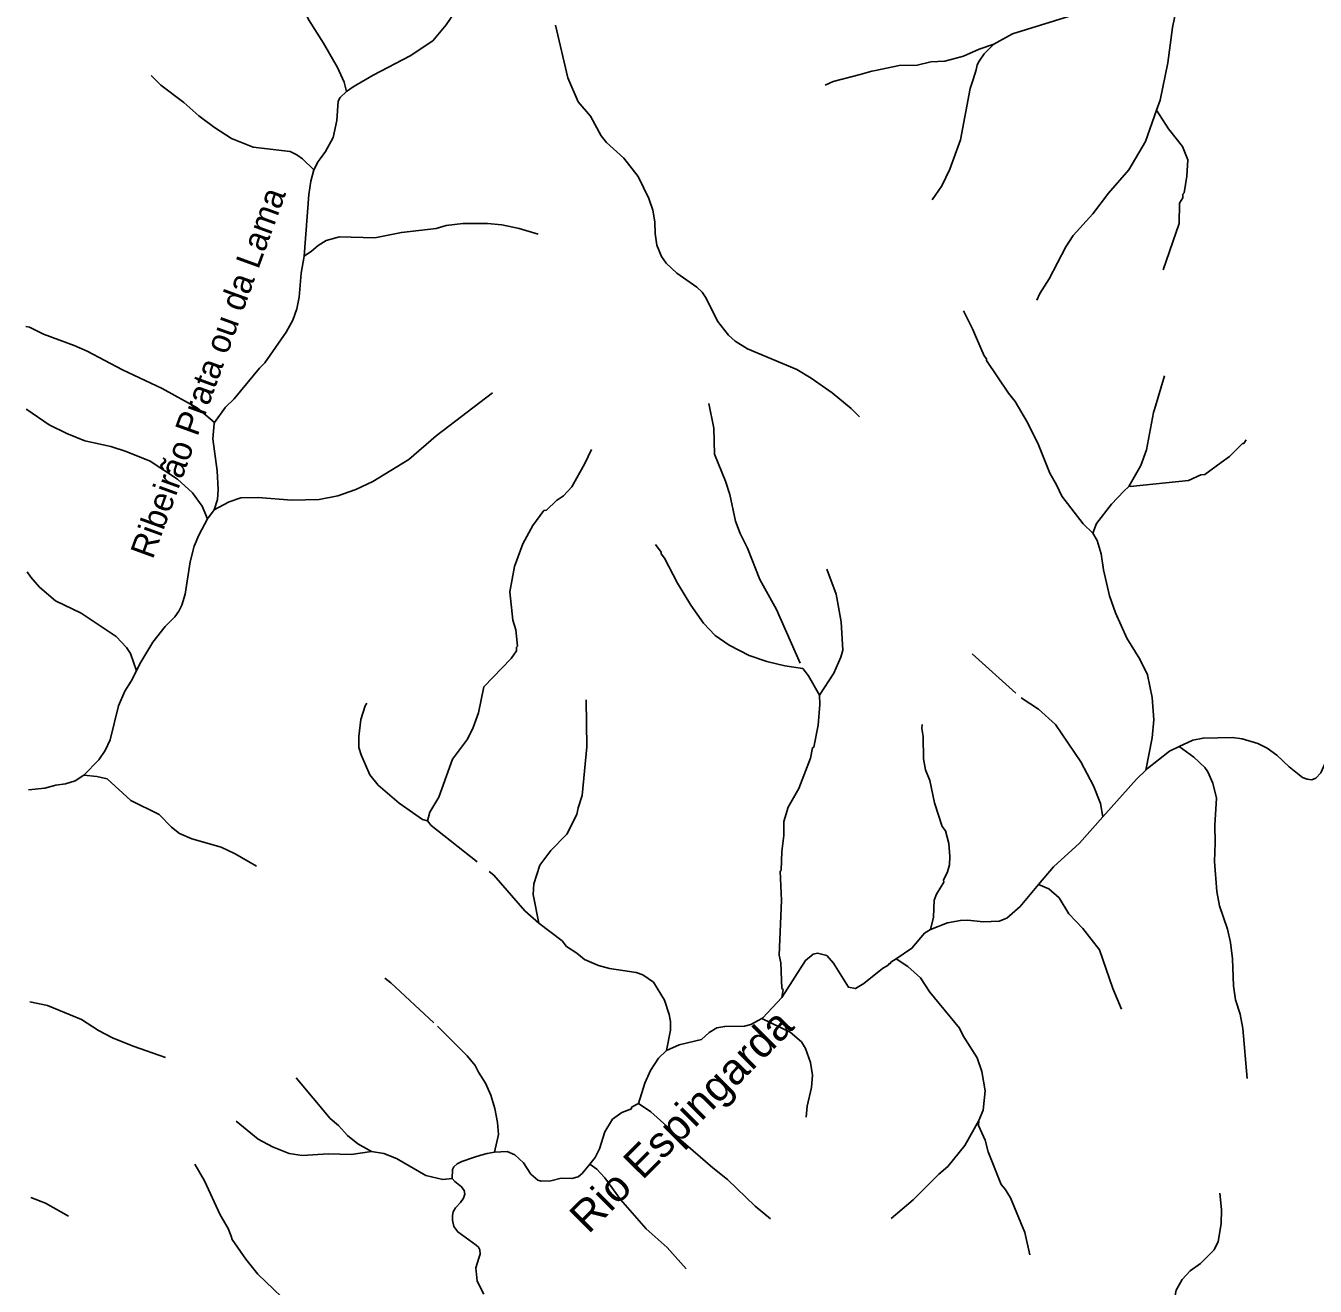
# Model space of a CAD drawing. Extents: x 280.4 to 335.6, y 8893.9 to 8949.5.
# Drawn here: x 280.52 to 288.97, y 8929.23 to 8937.49 of the extents above; entities that cross this region are included whole.
import ezdxf
from ezdxf.enums import TextEntityAlignment as Align

# ---------------------------------------------------------------- set-up
doc = ezdxf.new("R2010")
doc.units = 0
doc.header["$LTSCALE"] = 0.064
doc.linetypes.add('LONG_DASHED', pattern=[7.5, 6, -1.5])
doc.layers.add('61', color=7, linetype='Continuous')
doc.layers.add('7', color=7, linetype='Continuous', lineweight=25)
doc.layers.add('9', color=7, linetype='LONG_DASHED', lineweight=25)

msp = doc.modelspace()

# ---------------------------------------------------------------- linework, layer by layer
at = {"layer": '7'}
msp.add_line((281.7518, 8934.3135), (281.7096, 8934.2547), dxfattribs=at)
for points in [[(281.967, 8938.9139), (281.9473, 8938.7988), (281.9521, 8938.6717), (282.0016, 8938.4595), (282.0238, 8938.3645), (282.1057, 8938.1592), (282.2165, 8937.9498), (282.2476, 8937.8705), (282.2972, 8937.696), (282.3705, 8937.5274), (282.4689, 8937.3717), (282.5597, 8937.2125), (282.6042, 8937.1171), (282.6197, 8937.0564)], [(282.6197, 8937.0564), (282.6415, 8937.0718), (282.6624, 8937.0855), (282.7939, 8937.1632), (283.0361, 8937.2893), (283.1847, 8937.388), (283.2726, 8937.4919), (283.4685, 8937.7801)], [(285.9795, 8934.9237), (285.9257, 8934.9786), (285.8014, 8935.0821), (285.663, 8935.1783), (285.5691, 8935.2351), (285.2459, 8935.3688), (285.1656, 8935.4208), (285.122, 8935.4595), (285.0489, 8935.5507), (284.9765, 8935.702), (284.9485, 8935.7415), (284.9153, 8935.773), (284.7827, 8935.8659), (284.7124, 8935.9298), (284.6835, 8935.9743), (284.6516, 8936.0481), (284.6403, 8936.1257), (284.6387, 8936.2016), (284.6258, 8936.2792), (284.6007, 8936.3545), (284.5304, 8936.4985), (284.4369, 8936.619), (284.3233, 8936.722), (284.2866, 8936.7663), (284.2185, 8936.895), (284.1372, 8936.9881), (284.0697, 8937.1445), (283.9876, 8937.4914)], [(281.3389, 8937.1603), (281.4028, 8937.0978), (281.5546, 8936.9844), (281.6524, 8936.8962), (281.7549, 8936.8189), (281.8667, 8936.7474), (282.0086, 8936.6914), (282.2502, 8936.6619), (282.2942, 8936.6414), (282.331, 8936.6142), (282.4048, 8936.5418)], [(282.4048, 8936.5418), (282.4346, 8936.597), (282.4537, 8936.6241), (282.4813, 8936.6623), (282.5315, 8936.7535), (282.5564, 8936.8662), (282.5651, 8936.9922), (282.5772, 8937.0165), (282.6197, 8937.0564)], [(282.3422, 8935.9758), (282.3726, 8936.38), (282.3855, 8936.4672), (282.4048, 8936.5418)], [(283.8759, 8936.12), (283.7496, 8936.1584), (283.6363, 8936.181), (283.5424, 8936.1903), (283.3824, 8936.1904), (283.2726, 8936.1784), (283.2063, 8936.1581), (282.9787, 8936.1329), (282.806, 8936.0978), (282.5742, 8936.1038), (282.4867, 8936.0787), (282.4329, 8936.0477), (282.3911, 8936.0093), (282.3422, 8935.9758)], [(281.7555, 8934.8857), (281.8277, 8934.9864), (281.8842, 8935.0417), (282.0485, 8935.2427), (282.0836, 8935.278), (282.2243, 8935.4795), (282.2673, 8935.5563), (282.2942, 8935.6323), (282.3085, 8935.7084), (282.3233, 8935.8643), (282.3422, 8935.9758)], [(280.5185, 8935.5165), (280.5422, 8935.5104), (280.6336, 8935.4647), (280.8357, 8935.3908), (280.9195, 8935.3536), (281.1518, 8935.2329), (281.4121, 8935.109), (281.6417, 8934.983), (281.7555, 8934.8857)], [(283.5753, 8935.0811), (283.2068, 8934.8001), (283.027, 8934.6446), (282.7926, 8934.4997), (282.6808, 8934.4484), (282.5622, 8934.4056), (282.4398, 8934.3828), (282.2615, 8934.377), (282.0416, 8934.3961), (281.9272, 8934.393), (281.8504, 8934.3676), (281.8129, 8934.3474), (281.7518, 8934.3135)], [(280.5217, 8934.9745), (280.5243, 8934.9727), (280.6721, 8934.8714), (280.7864, 8934.8142), (280.9052, 8934.7665), (281.075, 8934.7305), (281.1769, 8934.6965), (281.3325, 8934.6329), (281.5122, 8934.5144), (281.6104, 8934.4258), (281.6732, 8934.3376), (281.7096, 8934.2547)], [(281.7518, 8934.3135), (281.7747, 8934.3822), (281.7785, 8934.4484), (281.7729, 8934.5704), (281.7427, 8934.7798), (281.7523, 8934.8812), (281.7555, 8934.8857)], [(281.2433, 8933.2589), (281.2666, 8933.3045), (281.3504, 8933.4471), (281.4307, 8933.5501), (281.4942, 8933.6139), (281.5213, 8933.6502), (281.5407, 8933.6901), (281.5618, 8933.7612), (281.5956, 8933.9731), (281.6223, 8934.0771), (281.6517, 8934.1489), (281.7096, 8934.2547)], [(280.5279, 8933.9075), (280.5517, 8933.8727), (280.6091, 8933.8086), (280.713, 8933.719), (280.8821, 8933.638), (281.1102, 8933.4851), (281.179, 8933.4131), (281.2054, 8933.3719), (281.2433, 8933.2589)], [(280.8997, 8932.5762), (280.9962, 8932.6757), (281.0388, 8932.7377), (281.0702, 8932.8065), (281.1265, 8933.0303), (281.1666, 8933.1271), (281.209, 8933.1919), (281.2433, 8933.2589)], [(289.193, 8932.8412), (289.1727, 8932.841), (289.1187, 8932.8127), (289.1163, 8932.8003), (289.1016, 8932.7925), (289.07, 8932.7449), (289.0018, 8932.5912), (288.9694, 8932.5555), (288.9433, 8932.5459), (288.9115, 8932.5491), (288.8818, 8932.5612), (288.7945, 8932.631), (288.7147, 8932.7061), (288.6507, 8932.7524), (288.5889, 8932.784), (288.4859, 8932.813), (288.4226, 8932.8224), (288.23, 8932.8191), (288.1639, 8932.8053), (288.0744, 8932.7635)], [(288.0744, 8932.7635), (288.0112, 8932.7339), (287.8666, 8932.6199), (287.8557, 8932.6094)], [(280.5362, 8932.4799), (280.6433, 8932.4909), (280.7143, 8932.5105), (280.7788, 8932.5188), (280.8414, 8932.5392), (280.8997, 8932.5762)], [(282.0295, 8931.9786), (281.8896, 8932.061), (281.7991, 8932.104), (281.6072, 8932.1586), (281.5251, 8932.1925), (281.473, 8932.2354), (281.3922, 8932.3186), (281.2069, 8932.4094), (281.0522, 8932.5507), (280.9836, 8932.5664), (280.8997, 8932.5762)], [(287.8557, 8932.6094), (287.794, 8932.5501), (287.5737, 8932.3016)], [(287.5737, 8932.3016), (287.421, 8932.1294), (287.2498, 8931.9743), (287.153, 8931.8589)], [(287.153, 8931.8589), (287.0328, 8931.7157), (286.9455, 8931.6393), (286.8937, 8931.6198), (286.7899, 8931.6135), (286.689, 8931.6261), (286.6404, 8931.6233), (286.5571, 8931.6073), (286.4442, 8931.5636)], [(286.4442, 8931.5636), (286.4064, 8931.5412), (286.3232, 8931.4414), (286.219, 8931.3726)], [(286.219, 8931.3726), (286.1854, 8931.3504), (286.1832, 8931.342), (286.1743, 8931.3411), (286.1681, 8931.3313), (286.1312, 8931.3085), (286.0087, 8931.2099), (285.9533, 8931.177), (285.9085, 8931.1854), (285.809, 8931.3437), (285.7651, 8931.3936), (285.7055, 8931.4085), (285.6764, 8931.4027), (285.6253, 8931.3618), (285.4711, 8931.1195), (285.47, 8931.1183)], [(281.434, 8930.725), (281.2209, 8930.7989), (281.0861, 8930.8542), (280.995, 8930.9022), (280.8837, 8930.9736), (280.6614, 8931.0669), (280.5444, 8931.0912)], [(285.47, 8931.1183), (285.3457, 8930.9854), (285.3397, 8930.982)], [(285.3397, 8930.982), (285.268, 8930.9415), (285.2256, 8930.9309), (285.0968, 8930.929), (285.0444, 8930.919), (284.9956, 8930.8904), (284.9445, 8930.8429), (284.7995, 8930.8086), (284.7162, 8930.7708)], [(284.7162, 8930.7708), (284.6632, 8930.7211), (284.6097, 8930.6403), (284.5735, 8930.5569), (284.5328, 8930.4241), (284.5312, 8930.4232)], [(284.5312, 8930.4232), (284.487, 8930.3994), (284.4859, 8930.3883), (284.4239, 8930.3655), (284.3614, 8930.3206), (284.3126, 8930.238), (284.2757, 8930.1277), (284.2488, 8930.0708), (284.2135, 8930.0274)], [(283.4505, 8930.0706), (283.3752, 8930.043), (283.3434, 8930.0277), (283.3222, 8930.01), (283.3145, 8929.9913), (283.3124, 8929.9327)], [(283.5892, 8930.1052), (283.5405, 8930.0958), (283.4987, 8930.0863), (283.4505, 8930.0706)], [(284.2135, 8930.0274), (284.1635, 8929.966), (284.1373, 8929.9435), (284.0957, 8929.9327), (284.0264, 8929.9354), (283.9583, 8929.9179), (283.8942, 8929.915), (283.8735, 8929.9206), (283.8279, 8929.9611), (283.7787, 8930.036), (283.7224, 8930.0876), (283.6714, 8930.1099), (283.5892, 8930.1052)], [(283.3124, 8929.9327), (283.3294, 8929.9132), (283.373, 8929.8785), (283.3909, 8929.8546), (283.3943, 8929.8303), (283.3866, 8929.8039), (283.3663, 8929.7744), (283.3332, 8929.74), (283.3178, 8929.7143), (283.3128, 8929.6891), (283.3131, 8929.6592), (283.3215, 8929.6178), (283.3481, 8929.5826), (283.4681, 8929.4956), (283.4834, 8929.4816), (283.4931, 8929.4643), (283.4949, 8929.4358), (283.4873, 8929.4113), (283.4667, 8929.3472), (283.4743, 8929.2592), (283.519, 8929.1736)], [(280.5519, 8929.8073), (280.6477, 8929.7706), (280.799, 8929.6847)]]:
    msp.add_lwpolyline(points, dxfattribs=at)
at = {"layer": '9'}
for points in [[(286.86, 8937.3667), (286.9819, 8937.4331), (287.3632, 8937.5528), (287.5977, 8937.6453), (287.7712, 8937.7255), (288.0004, 8937.8186), (288.0644, 8937.861)], [(287.9256, 8936.9331), (287.9492, 8936.9999), (288.0006, 8937.2435), (288.031, 8937.4755), (288.0551, 8937.5918), (288.0676, 8937.7185), (288.0644, 8937.861)], [(285.7555, 8937.0966), (285.808, 8937.1208), (285.9839, 8937.1681), (286.0596, 8937.1887), (286.0851, 8937.1941), (286.2388, 8937.2267), (286.3581, 8937.2286), (286.4469, 8937.2506), (286.5396, 8937.2555), (286.662, 8937.2871), (286.7627, 8937.3323), (286.86, 8937.3667)], [(286.4557, 8936.3456), (286.5201, 8936.4378), (286.5711, 8936.5464), (286.6412, 8936.7381), (286.7048, 8937.0756), (286.7242, 8937.1341), (286.7435, 8937.1973), (286.7514, 8937.2306), (286.763, 8937.2538), (286.7968, 8937.3026), (286.86, 8937.3667)], [(287.1408, 8935.689), (287.1613, 8935.7315), (287.2232, 8935.8275), (287.3308, 8936.0377), (287.3804, 8936.1129), (287.5084, 8936.2533), (287.6118, 8936.3887), (287.7437, 8936.5422), (287.8533, 8936.7279), (287.9256, 8936.9331)], [(287.9689, 8935.8863), (288.0728, 8936.1917), (288.0766, 8936.3232), (288.0989, 8936.3593), (288.0983, 8936.3837), (288.1061, 8936.3919), (288.1237, 8936.5007), (288.1315, 8936.6079), (288.0965, 8936.6952), (288.0032, 8936.8115), (287.9256, 8936.9331)], [(286.6608, 8935.6181), (286.7204, 8935.5007), (286.7466, 8935.4398), (286.7964, 8935.3243), (286.8122, 8935.3044), (286.8112, 8935.293), (286.955, 8935.0799), (286.9988, 8935.0245), (287.0812, 8934.8878), (287.1528, 8934.7399), (287.2277, 8934.5551), (287.2711, 8934.4791), (287.3045, 8934.4032), (287.4447, 8934.2227), (287.5093, 8934.1605)], [(287.9776, 8935.1933), (287.912, 8934.9713), (287.9064, 8934.9523), (287.859, 8934.7073), (287.8226, 8934.605), (287.7434, 8934.4663)], [(284.9924, 8935.0108), (285.0253, 8934.8495), (285.0307, 8934.6796), (285.1025, 8934.5016), (285.1295, 8934.4145), (285.1666, 8934.2409), (285.1982, 8934.1602), (285.2468, 8934.0627), (285.3265, 8933.8572), (285.4368, 8933.6604), (285.6076, 8933.2739)], [(288.5134, 8934.7726), (288.4979, 8934.7483), (288.489, 8934.7483), (288.4029, 8934.6643), (288.3482, 8934.6244), (288.2418, 8934.5467), (288.2155, 8934.5428), (288.1344, 8934.5063), (287.7434, 8934.4663)], [(284.224, 8934.7102), (284.181, 8934.6179), (284.0948, 8934.4646), (284.04, 8934.4067), (283.9955, 8934.3749), (283.9294, 8934.3121), (283.9131, 8934.3095), (283.8395, 8934.2127), (283.7738, 8934.0913), (283.7203, 8933.9441), (283.689, 8933.778), (283.7096, 8933.5924), (283.7288, 8933.5277), (283.74, 8933.4218), (283.7338, 8933.4134), (283.7335, 8933.3908), (283.6973, 8933.3411), (283.5183, 8933.1539), (283.4839, 8932.9832), (283.4492, 8932.8887), (283.4116, 8932.8121), (283.3147, 8932.6816), (283.2237, 8932.4313), (283.1645, 8932.3323), (283.1502, 8932.2762)], [(287.7434, 8934.4663), (287.7116, 8934.4369), (287.6297, 8934.3516), (287.5322, 8934.2256), (287.5093, 8934.1605)], [(284.6439, 8934.0867), (284.6799, 8934.0375), (284.681, 8934.0263), (284.7025, 8933.9977), (284.7867, 8933.8343), (284.875, 8933.6907), (284.9582, 8933.5715), (285.0349, 8933.4899), (285.1252, 8933.4278), (285.2577, 8933.3607), (285.3722, 8933.3216), (285.4913, 8933.293), (285.6076, 8933.2739)], [(287.5093, 8934.1605), (287.5363, 8934.1143), (287.5624, 8934.0259), (287.5786, 8933.9204), (287.617, 8933.7508), (287.6569, 8933.6404), (287.7319, 8933.4729), (287.8169, 8933.3351), (287.8671, 8933.2333), (287.8964, 8933.0839), (287.9076, 8932.9392), (287.898, 8932.8208), (287.8557, 8932.6094)], [(285.7175, 8933.099), (285.811, 8933.2447), (285.8571, 8933.3479), (285.87, 8933.395), (285.8607, 8933.5812), (285.8271, 8933.7622), (285.7663, 8933.926)], [(286.7187, 8933.3704), (287.0383, 8933.0827), (287.1528, 8933.0079), (287.2637, 8932.908), (287.4304, 8932.6636), (287.5134, 8932.5057), (287.5587, 8932.3898), (287.5737, 8932.3016)], [(285.6076, 8933.2739), (285.6461, 8933.227), (285.7175, 8933.099)], [(285.7175, 8933.099), (285.721, 8933.0395), (285.7083, 8932.9039), (285.6815, 8932.7601), (285.672, 8932.7558), (285.6591, 8932.6866), (285.5814, 8932.4879), (285.5121, 8932.3666), (285.4852, 8932.2722), (285.4851, 8932.1807), (285.4705, 8932.0755), (285.4672, 8931.9502), (285.4611, 8931.946), (285.4688, 8931.7552), (285.4546, 8931.3967), (285.464, 8931.3456), (285.472, 8931.1766), (285.4797, 8931.1703), (285.47, 8931.1183)], [(282.7536, 8933.0475), (282.7419, 8933.0298), (282.7135, 8932.9398), (282.7006, 8932.8287), (282.7005, 8932.7565), (282.7147, 8932.7095), (282.7729, 8932.5785), (282.8266, 8932.5109), (282.9647, 8932.3912), (283.1167, 8932.2859), (283.1502, 8932.2762)], [(284.1887, 8933.0697), (284.1942, 8932.7607), (284.1639, 8932.4425), (284.1365, 8932.361), (284.1285, 8932.3171), (284.0627, 8932.1892), (283.9579, 8932.0821), (283.8851, 8931.9858), (283.8473, 8931.8628), (283.8425, 8931.7931), (283.8792, 8931.6063)], [(286.3903, 8932.9079), (286.3888, 8932.8812), (286.3979, 8932.8287), (286.3996, 8932.6827), (286.4113, 8932.61), (286.4415, 8932.5409), (286.4705, 8932.3941), (286.5223, 8932.2401), (286.543, 8932.2108), (286.5643, 8932.1283), (286.5722, 8932.0427), (286.569, 8931.9885), (286.5567, 8931.9412), (286.5306, 8931.8872), (286.5314, 8931.8738), (286.4847, 8931.7948), (286.47, 8931.7557), (286.4648, 8931.6453), (286.4442, 8931.5636)], [(288.5203, 8930.5883), (288.4916, 8930.9164), (288.4724, 8931.0096), (288.4418, 8931.1025), (288.429, 8931.1952), (288.4226, 8931.3719), (288.4096, 8931.479), (288.3912, 8931.5657), (288.3377, 8931.7198), (288.32, 8931.8139), (288.3044, 8932.0109), (288.3106, 8932.1331), (288.3083, 8932.2476), (288.3188, 8932.4251), (288.2947, 8932.5233), (288.261, 8932.5973), (288.2417, 8932.6249), (288.1699, 8932.6928), (288.0744, 8932.7635)], [(283.1502, 8932.2762), (283.1742, 8932.2466), (283.5854, 8931.9198), (283.7875, 8931.6859), (283.8792, 8931.6063)], [(287.6965, 8931.0421), (287.6386, 8931.1781), (287.5512, 8931.4305), (287.442, 8931.5704), (287.3512, 8931.6678), (287.2867, 8931.7721), (287.2208, 8931.8301), (287.153, 8931.8589)], [(283.8792, 8931.6063), (284.0313, 8931.4897), (284.0606, 8931.453), (284.1286, 8931.4094), (284.1783, 8931.3669), (284.2701, 8931.3275), (284.3424, 8931.3085), (284.5179, 8931.282), (284.5605, 8931.2662), (284.6302, 8931.2186), (284.7023, 8931.1007), (284.7331, 8931.0072), (284.7411, 8930.9618), (284.7411, 8930.9057), (284.7162, 8930.7708)], [(286.7617, 8930.3132), (286.791, 8930.3795), (286.8023, 8930.5079), (286.7818, 8930.6339), (286.751, 8930.7232), (286.6587, 8930.8682), (286.6353, 8930.9177), (286.4413, 8931.1531), (286.3792, 8931.2465), (286.2956, 8931.3223), (286.219, 8931.3726)], [(282.8704, 8931.2444), (282.9096, 8931.215), (283.2144, 8930.9315), (283.4105, 8930.7369), (283.4628, 8930.6736), (283.4834, 8930.6283), (283.5299, 8930.5572), (283.5643, 8930.4779), (283.5914, 8930.3923), (283.6095, 8930.2987), (283.6153, 8930.2206), (283.5892, 8930.1052)], [(285.63, 8930.3338), (285.6377, 8930.407), (285.6655, 8930.5294), (285.6718, 8930.6099), (285.6591, 8930.6938), (285.627, 8930.7849), (285.5994, 8930.8285), (285.5248, 8930.8916), (285.3397, 8930.982)], [(282.2888, 8930.5913), (282.5127, 8930.325), (282.5661, 8930.2796), (282.6254, 8930.2141), (282.6935, 8930.1605), (282.7837, 8930.1103)], [(285.396, 8929.6677), (285.2957, 8929.7518), (285.1151, 8929.9265), (285.0182, 8930.0023), (284.761, 8930.2247), (284.7184, 8930.2766), (284.6121, 8930.3691), (284.5312, 8930.4232)], [(281.8967, 8930.309), (282.0413, 8930.1898), (282.1356, 8930.1399), (282.2434, 8930.0969), (282.3297, 8930.0831), (282.5014, 8930.094), (282.6493, 8930.0894), (282.7837, 8930.1103)], [(286.1866, 8929.6705), (286.3307, 8929.7935), (286.4994, 8929.9603), (286.5595, 8930.0111), (286.6689, 8930.1495), (286.7617, 8930.3132)], [(287.0955, 8929.4316), (287.063, 8929.5782), (286.9683, 8929.8055), (286.9341, 8929.8631), (286.9079, 8929.8934), (286.8231, 8930.1072), (286.8035, 8930.1836), (286.7587, 8930.2803), (286.7617, 8930.3132)], [(282.7837, 8930.1103), (282.8637, 8930.0964), (282.9476, 8930.0626), (283.139, 8929.9525), (283.2508, 8929.9271), (283.3124, 8929.9327)], [(281.6252, 8930.0258), (281.6897, 8929.9165), (281.7916, 8929.6939), (281.8432, 8929.6047), (281.8628, 8929.5543), (281.8709, 8929.5336), (281.9607, 8929.4039), (282.0378, 8929.3064), (282.2442, 8929.1094), (282.3008, 8929.0386), (282.5712, 8928.8222), (282.726, 8928.6772), (283.1133, 8928.2739), (283.1545, 8928.2173)], [(284.8442, 8929.3412), (284.7199, 8929.4803), (284.5824, 8929.6037), (284.4143, 8929.7945), (284.312, 8929.9379), (284.2597, 8929.9933), (284.2135, 8930.0274)], [(288.3395, 8929.8366), (288.352, 8929.7303), (288.3493, 8929.6365), (288.3296, 8929.5202), (288.3041, 8929.4656), (288.213, 8929.3762), (288.1463, 8929.3267), (288.0926, 8929.2714), (288.055, 8929.2016), (288.0388, 8929.1209), (288.0229, 8928.8489), (288.0107, 8928.7558)]]:
    msp.add_lwpolyline(points, dxfattribs=at)

# ---------------------------------------------------------------- texts
at = {"layer": '61'}
msp.add_text('Ribeirão Prata ou da Lama', height=0.16, rotation=70.017, dxfattribs=at).set_placement((281.787, 8935.1866), align=Align.CENTER)
at = {"layer": '61', "width": 1.05}
msp.add_text('Rio Espingarda', height=0.2, rotation=45, dxfattribs=at).set_placement((284.8824, 8930.2427), align=Align.CENTER)

doc.saveas('drawing.dxf')
